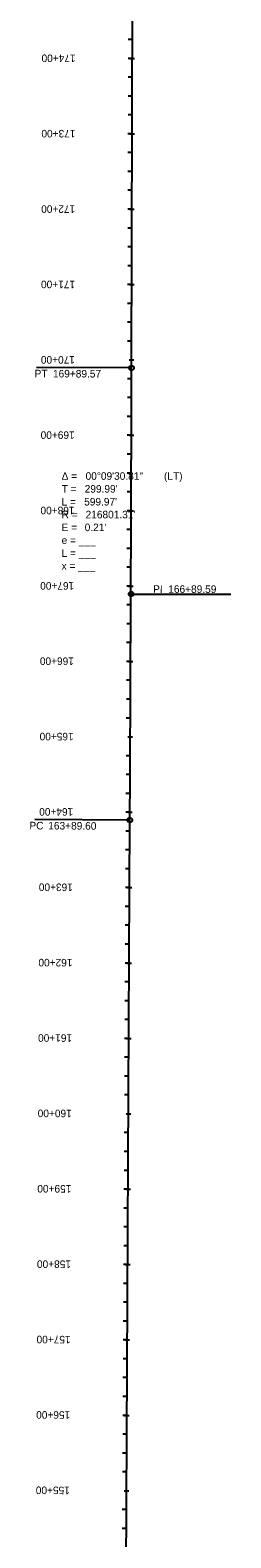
# Model space of a CAD drawing. Extents: x 23417911 to 23421158, y 6737892 to 6791804.
# Drawn here: x 23418159 to 23418425, y 6741912 to 6743912 of the extents above; entities that cross this region are included whole.
import ezdxf

# ---------------------------------------------------------------- set-up
doc = ezdxf.new("R2010")
doc.units = 0
for name, color, linetype in [('Alignment', 7, 'Continuous'), ('TextAlignment', 7, 'Continuous'), ('TextAlignmentLrg', 7, 'Continuous'), ('TextAlignmentSml', 7, 'Continuous')]:
    doc.layers.add(name, color=color, linetype=linetype)

msp = doc.modelspace()

# ---------------------------------------------------------------- linework, layer by layer
at = {"layer": 'Alignment'}
for p, q in [((23418293.5, 6743464.3), (23418298.5, 6745664.9)), ((23418293.5, 6743464.3), (23418298.5, 6745664.9)), ((23418281, 6740831.6), (23418291.3, 6742864.4)), ((23418281, 6740831.6), (23418291.3, 6742864.4))]:
    msp.add_line(p, q, dxfattribs=at)
msp.add_arc((23201492.7, 6743957.4), 216801.3, 359.711135, 359.869694, dxfattribs=at)
msp.add_arc((23201492.7, 6743957.4), 216801.3, 359.711135, 359.869694, dxfattribs=at)
at = {"layer": 'TextAlignment'}
for p, q in [((23418293.5, 6743464.3), (23418167.5, 6743464.6)), ((23418167.5, 6743464.6), (23418167.5, 6743464.6)), ((23418292.8, 6743164.3), (23418424.8, 6743163.9)), ((23418424.8, 6743163.9), (23418424.8, 6743163.9)), ((23418291.3, 6742864.4), (23418165.3, 6742865)), ((23418165.3, 6742865), (23418165.3, 6742865))]:
    msp.add_line(p, q, dxfattribs=at)
for centre in [(23418293.5, 6743464.3), (23418292.8, 6743164.3), (23418291.3, 6742864.4)]:
    msp.add_circle(centre, 3.12, dxfattribs=at)
at = {"layer": 'TextAlignmentLrg'}
for p, q in [((23418294.4, 6743874.8), (23418288.9, 6743874.8)), ((23418294.2, 6743774.8), (23418288.7, 6743774.8)), ((23418293.9, 6743674.8), (23418288.5, 6743674.8)), ((23418293.7, 6743574.8), (23418288.2, 6743574.8)), ((23418290.4, 6743474.8), (23418296.5, 6743474.8)), ((23418293.2, 6743374.8), (23418287.8, 6743374.8)), ((23418292.9, 6743274.8), (23418287.5, 6743274.8)), ((23418292.6, 6743174.8), (23418287.1, 6743174.8)), ((23418292.2, 6743074.8), (23418286.8, 6743074.8)), ((23418288.7, 6742974.8), (23418294.9, 6742974.8)), ((23418291.3, 6742874.8), (23418285.9, 6742874.8)), ((23418290.8, 6742774.8), (23418285.4, 6742774.8)), ((23418290.3, 6742674.8), (23418284.8, 6742674.8)), ((23418289.8, 6742574.8), (23418284.3, 6742574.8)), ((23418286.2, 6742474.8), (23418292.4, 6742474.8)), ((23418288.8, 6742374.8), (23418283.3, 6742374.8)), ((23418288.3, 6742274.8), (23418282.8, 6742274.8)), ((23418287.8, 6742174.8), (23418282.3, 6742174.8)), ((23418287.3, 6742074.8), (23418281.8, 6742074.8)), ((23418283.7, 6741974.8), (23418289.8, 6741974.8))]:
    msp.add_line(p, q, dxfattribs=at)
at = {"layer": 'TextAlignmentSml'}
for p, q in [((23418294.4, 6743899.8), (23418289, 6743899.8)), ((23418291.3, 6743874.8), (23418297.5, 6743874.8)), ((23418294.3, 6743849.8), (23418288.9, 6743849.8)), ((23418294.3, 6743824.8), (23418288.8, 6743824.8)), ((23418294.2, 6743799.8), (23418288.8, 6743799.8)), ((23418291.1, 6743774.8), (23418297.2, 6743774.8)), ((23418294.1, 6743749.8), (23418288.6, 6743749.8)), ((23418294.1, 6743724.8), (23418288.6, 6743724.8)), ((23418294, 6743699.8), (23418288.5, 6743699.8)), ((23418290.9, 6743674.8), (23418297, 6743674.8)), ((23418293.9, 6743649.8), (23418288.4, 6743649.8)), ((23418293.8, 6743624.8), (23418288.4, 6743624.8)), ((23418293.8, 6743599.8), (23418288.3, 6743599.8)), ((23418290.6, 6743574.8), (23418296.8, 6743574.8)), ((23418293.7, 6743549.8), (23418288.2, 6743549.8)), ((23418293.6, 6743524.8), (23418288.1, 6743524.8)), ((23418293.5, 6743499.8), (23418288.1, 6743499.8)), ((23418290.4, 6743474.8), (23418296.5, 6743474.8)), ((23418293.4, 6743449.8), (23418288, 6743449.8)), ((23418293.4, 6743424.8), (23418287.9, 6743424.8)), ((23418293.3, 6743399.8), (23418287.8, 6743399.8)), ((23418290.2, 6743374.8), (23418296.3, 6743374.8)), ((23418293.2, 6743349.8), (23418287.7, 6743349.8)), ((23418293.1, 6743324.8), (23418287.6, 6743324.8)), ((23418293, 6743299.8), (23418287.6, 6743299.8)), ((23418289.9, 6743274.8), (23418296, 6743274.8)), ((23418292.9, 6743249.8), (23418287.4, 6743249.8)), ((23418292.8, 6743224.8), (23418287.3, 6743224.8)), ((23418292.7, 6743199.8), (23418287.2, 6743199.8)), ((23418289.5, 6743174.8), (23418295.7, 6743174.8)), ((23418292.5, 6743149.8), (23418287.1, 6743149.8)), ((23418292.4, 6743124.8), (23418287, 6743124.8)), ((23418292.3, 6743099.8), (23418286.9, 6743099.8)), ((23418289.2, 6743074.8), (23418295.3, 6743074.8)), ((23418292.1, 6743049.8), (23418286.7, 6743049.8)), ((23418292, 6743024.8), (23418286.6, 6743024.8)), ((23418291.9, 6742999.8), (23418286.4, 6742999.8)), ((23418288.7, 6742974.8), (23418294.9, 6742974.8)), ((23418291.7, 6742949.8), (23418286.2, 6742949.8)), ((23418291.6, 6742924.8), (23418286.1, 6742924.8)), ((23418291.4, 6742899.8), (23418286, 6742899.8)), ((23418288.3, 6742874.8), (23418294.4, 6742874.8)), ((23418291.2, 6742849.8), (23418285.7, 6742849.8)), ((23418291.1, 6742824.8), (23418285.6, 6742824.8)), ((23418290.9, 6742799.8), (23418285.5, 6742799.8)), ((23418287.8, 6742774.8), (23418293.9, 6742774.8)), ((23418290.7, 6742749.8), (23418285.2, 6742749.8)), ((23418290.6, 6742724.8), (23418285.1, 6742724.8)), ((23418290.4, 6742699.8), (23418285, 6742699.8)), ((23418287.2, 6742674.8), (23418293.4, 6742674.8)), ((23418290.2, 6742649.8), (23418284.7, 6742649.8)), ((23418290.1, 6742624.8), (23418284.6, 6742624.8)), ((23418289.9, 6742599.8), (23418284.5, 6742599.8)), ((23418286.7, 6742574.8), (23418292.9, 6742574.8)), ((23418289.7, 6742549.8), (23418284.2, 6742549.8)), ((23418289.6, 6742524.8), (23418284.1, 6742524.8)), ((23418289.4, 6742499.8), (23418284, 6742499.8)), ((23418286.2, 6742474.8), (23418292.4, 6742474.8)), ((23418289.2, 6742449.8), (23418283.7, 6742449.8)), ((23418289, 6742424.8), (23418283.6, 6742424.8)), ((23418288.9, 6742399.8), (23418283.5, 6742399.8)), ((23418285.7, 6742374.8), (23418291.9, 6742374.8)), ((23418288.7, 6742349.8), (23418283.2, 6742349.8)), ((23418288.5, 6742324.8), (23418283.1, 6742324.8)), ((23418288.4, 6742299.8), (23418283, 6742299.8)), ((23418285.2, 6742274.8), (23418291.4, 6742274.8)), ((23418288.2, 6742249.8), (23418282.7, 6742249.8)), ((23418288, 6742224.8), (23418282.6, 6742224.8)), ((23418287.9, 6742199.8), (23418282.5, 6742199.8)), ((23418284.7, 6742174.8), (23418290.8, 6742174.8)), ((23418287.7, 6742149.8), (23418282.2, 6742149.8)), ((23418287.5, 6742124.8), (23418282.1, 6742124.8)), ((23418287.4, 6742099.8), (23418281.9, 6742099.8)), ((23418284.2, 6742074.8), (23418290.3, 6742074.8)), ((23418287.2, 6742049.8), (23418281.7, 6742049.8)), ((23418287, 6742024.8), (23418281.6, 6742024.8)), ((23418286.9, 6741999.8), (23418281.4, 6741999.8)), ((23418283.7, 6741974.8), (23418289.8, 6741974.8)), ((23418286.7, 6741949.8), (23418281.2, 6741949.8)), ((23418286.5, 6741924.8), (23418281.1, 6741924.8))]:
    msp.add_line(p, q, dxfattribs=at)

# ---------------------------------------------------------------- texts
at = {"layer": 'TextAlignment'}
for s, rotation, p in [('PT', 359.8697, (23418165.1, 6743451.7)), ('169+89.57', 359.8697, (23418189.4, 6743451.6)), ('PI ', 359.7904, (23418322, 6743165.9)), ('166+89.59', 359.7904, (23418342, 6743165.9)), ('PC', 359.7111, (23418158.2, 6742852.1)), ('163+89.60', 359.7111, (23418183.2, 6742852))]:
    msp.add_text(s, height=10.02, rotation=rotation, dxfattribs=at).set_placement(p)
for s, p in [('Δ = ', (23418200.9, 6743315.8)), ('00°09\'30.81"', (23418232.6, 6743315.8)), (' (LT)', (23418332.6, 6743315.8)), ('T = ', (23418200.9, 6743298.8)), ("299.99'", (23418231.4, 6743298.8)), ('L = ', (23418200.9, 6743281.7)), ("599.97'", (23418230.7, 6743281.7)), ('R = ', (23418200.9, 6743264.7)), ('E = ', (23418200.9, 6743247.7)), ("0.21'", (23418231.4, 6743247.7)), ("216801.31'", (23418232.6, 6743264.7)), ('e = ___ ', (23418200.9, 6743230.6)), ('L = ___', (23418200.9, 6743213.6)), ('x = ___', (23418200.9, 6743196.5))]:
    msp.add_text(s, height=10.02, dxfattribs=at).set_placement(p)
at = {"layer": 'TextAlignmentLrg'}
for s, rotation, p in [('170+00', 179.8697, (23418218.5, 6743479.9)), ('165+00', 179.7403, (23418216.8, 6742980.1)), ('160+00', 179.7111, (23418214.3, 6742480.2)), ('155+00', 179.7111, (23418211.8, 6741980.2))]:
    msp.add_text(s, height=10.02, rotation=rotation, dxfattribs=at).set_placement(p)
at = {"layer": 'TextAlignmentSml'}
for s, rotation, p in [('174+00', 179.8697, (23418219.4, 6743879.9)), ('173+00', 179.8697, (23418219.2, 6743779.9)), ('172+00', 179.8697, (23418218.9, 6743679.9)), ('171+00', 179.8697, (23418218.7, 6743579.9)), ('170+00', 179.8697, (23418218.5, 6743479.9)), ('169+00', 179.846, (23418218.2, 6743380)), ('168+00', 179.8196, (23418218, 6743280)), ('167+00', 179.7932, (23418217.6, 6743180)), ('166+00', 179.7667, (23418217.2, 6743080.1)), ('165+00', 179.7403, (23418216.8, 6742980.1)), ('164+00', 179.7139, (23418216.3, 6742880.2)), ('163+00', 179.7111, (23418215.8, 6742780.2)), ('162+00', 179.7111, (23418215.3, 6742680.2)), ('161+00', 179.7111, (23418214.8, 6742580.2)), ('160+00', 179.7111, (23418214.3, 6742480.2)), ('159+00', 179.7111, (23418213.8, 6742380.2)), ('158+00', 179.7111, (23418213.3, 6742280.2)), ('157+00', 179.7111, (23418212.8, 6742180.2)), ('156+00', 179.7111, (23418212.3, 6742080.2)), ('155+00', 179.7111, (23418211.8, 6741980.2))]:
    msp.add_text(s, height=10.02, rotation=rotation, dxfattribs=at).set_placement(p)

doc.saveas('drawing.dxf')
